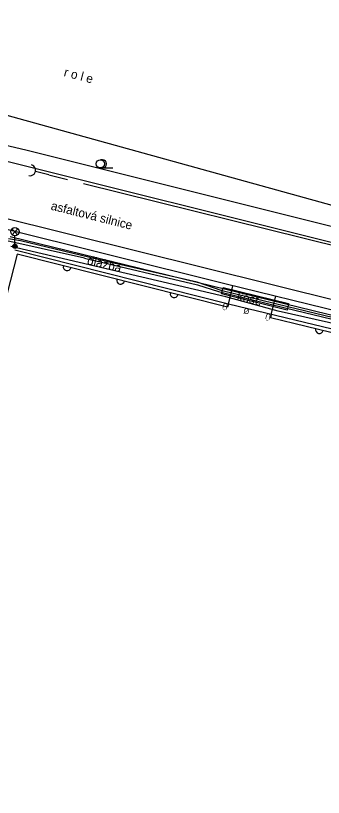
# Model space of a CAD drawing. Extents: x -614582 to -612559, y -1157748 to -1156203.
# Drawn here: x -612986.4 to -612958.6, y -1156940.7 to -1156869.8 of the extents above; entities that cross this region are included whole.
import ezdxf

# ---------------------------------------------------------------- set-up
doc = ezdxf.new("R2010")
doc.units = 0
for name, color, linetype in [('Vrstva 1', 7, 'Continuous'), ('Vrstva 11', 7, 'Continuous'), ('Vrstva 13', 7, 'Continuous'), ('Vrstva 17', 7, 'Continuous'), ('Vrstva 20', 7, 'Continuous'), ('Vrstva 22', 7, 'Continuous'), ('Vrstva 34', 7, 'Continuous'), ('Vrstva 36', 7, 'Continuous'), ('Vrstva 4', 7, 'Continuous'), ('Vrstva 47', 7, 'Continuous'), ('Vrstva 48', 7, 'Continuous'), ('Vrstva 5', 7, 'Continuous'), ('Vrstva 51', 7, 'Continuous'), ('Vrstva 7', 7, 'Continuous')]:
    doc.layers.add(name, color=color, linetype=linetype)

# ---------------------------------------------------------------- blocks, each defined once
blk = doc.blocks.new('SC3408')
at = {"layer": 'Vrstva 11'}
for points in [[(0, 5.5), (-2.5, 8)], [(0, 5.5), (2.5, 8)], [(0, 5.5), (-2.5, 3)], [(0, 5.5), (2.5, 3)], [(0, -5.5), (0, 2)]]:
    blk.add_lwpolyline(points, dxfattribs=at)
for centre, radius in [((0, 5.75), 3.75), ((0, -7.5), 2), ((0, -7.5), 1.6), ((0, -7.5), 1.2), ((0, -7.5), 0.8), ((0, -7.5), 0.4)]:
    blk.add_circle(centre, radius, dxfattribs=at)
blk = doc.blocks.new('PLOTZD')
at = {"layer": 'Vrstva 1'}
blk.add_arc((0, 0), 3.5, 0, 180, dxfattribs=at)
blk = doc.blocks.new('SC3420')
at = {"layer": 'Vrstva 48'}
for points in [[(0, 0), (-12.5, 0)], [(0, 0), (17.5, 0)]]:
    blk.add_lwpolyline(points, dxfattribs=at)
blk.add_arc((-17.5, 0), 5, 270, 90, dxfattribs=at)

msp = doc.modelspace()

# ---------------------------------------------------------------- linework, layer by layer
at = {"layer": 'Vrstva 17'}
msp.add_line((-612915.981, -1156905.926), (-613025.811, -1156878.626), dxfattribs=at)
at = {"layer": 'Vrstva 20'}
msp.add_line((-612917.45, -1156906.801), (-612986.931, -1156889.823), dxfattribs=at)
msp.add_line((-612917.45, -1156906.801), (-612986.931, -1156889.823), dxfattribs=at)
at = {"layer": 'Vrstva 22'}
for p, q in [((-613033.617, -1156870.174), (-612985.401, -1156881.987)), ((-612985.401, -1156881.987), (-612750.739, -1156940.65))]:
    msp.add_line(p, q, dxfattribs=at)
at = {"layer": 'Vrstva 34'}
for p, q in [((-612986.011, -1156890.196), (-612987.081, -1156890.016)), ((-612978.201, -1156892.056), (-612986.011, -1156890.196)), ((-612969.991, -1156893.936), (-612978.201, -1156892.056)), ((-612967.711, -1156894.716), (-612969.991, -1156893.936)), ((-612961.771, -1156896.176), (-612967.711, -1156894.716)), ((-612954.491, -1156897.926), (-612961.771, -1156896.176))]:
    msp.add_line(p, q, dxfattribs=at)
at = {"layer": 'Vrstva 36'}
msp.add_lwpolyline([(-612967.783, -1156895.007), (-612967.639, -1156894.425), (-612961.699, -1156895.885), (-612961.843, -1156896.467)], close=True, dxfattribs=at)
at = {"layer": 'Vrstva 4'}
for p, q in [((-612945.431, -1156890.396), (-613019.931, -1156869.776)), ((-613011.831, -1156876.856), (-612946.761, -1156893.076)), ((-612967.481, -1156894.096), (-612996.021, -1156886.996)), ((-612934.771, -1156902.106), (-612967.481, -1156894.096)), ((-612967.161, -1156895.926), (-612966.756, -1156894.274)), ((-612963.274, -1156896.871), (-612962.871, -1156895.225)), ((-612967.161, -1156895.926), (-612967.232, -1156896.218)), ((-612963.274, -1156896.871), (-612963.345, -1156897.163))]:
    msp.add_line(p, q, dxfattribs=at)
at = {"layer": 'Vrstva 47'}
for p, q in [((-612967.407, -1156895.263), (-612986.877, -1156890.714)), ((-612962.663, -1156896.564), (-612967.407, -1156895.263)), ((-612934.978, -1156902.854), (-612962.663, -1156896.564))]:
    msp.add_line(p, q, dxfattribs=at)
at = {"layer": 'Vrstva 48'}
msp.add_line((-612980.281, -1156885), (-612954.121, -1156891.496), dxfattribs=at)
at = {"layer": 'Vrstva 5'}
for p, q in [((-612967.161, -1156895.926), (-612986.511, -1156891.046)), ((-612986.295, -1156891.41), (-612987.804, -1156897.292)), ((-612967.233, -1156896.218), (-612986.295, -1156891.41)), ((-612934.551, -1156903.856), (-612967.161, -1156895.926)), ((-612934.622, -1156904.148), (-612963.345, -1156897.163))]:
    msp.add_line(p, q, dxfattribs=at)
at = {"layer": 'Vrstva 51'}
for p, q in [((-612980.213, -1156891.76), (-612988.091, -1156890.025)), ((-612980.213, -1156891.76), (-612988.091, -1156890.025)), ((-612980.213, -1156891.76), (-612969.957, -1156894.175)), ((-612980.213, -1156891.76), (-612969.957, -1156894.175)), ((-612969.957, -1156894.175), (-612968.046, -1156894.793)), ((-612969.957, -1156894.175), (-612968.046, -1156894.793)), ((-612968.046, -1156894.793), (-612962.005, -1156896.254)), ((-612968.046, -1156894.793), (-612962.005, -1156896.254)), ((-612962.005, -1156896.254), (-612951.044, -1156898.933)), ((-612962.005, -1156896.254), (-612951.044, -1156898.933))]:
    msp.add_line(p, q, dxfattribs=at)
at = {"layer": 'Vrstva 7'}
for points in [[(-612978.565, -1156882.846), (-612978.765, -1156882.846)], [(-612978.765, -1156883.579), (-612978.265, -1156883.579), (-612978.065, -1156883.579), (-612977.632, -1156883.579)]]:
    msp.add_lwpolyline(points, dxfattribs=at)
msp.add_circle((-612978.765, -1156883.212), 0.367, dxfattribs=at)
msp.add_arc((-612978.565, -1156883.212), 0.367, 270, 90, dxfattribs=at)

# ---------------------------------------------------------------- block references
at = {"layer": 'Vrstva 11', "xscale": 0.1, "yscale": 0.10000000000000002}
msp.add_blockref('SC3408', (-612986.511, -1156889.936), dxfattribs=at)
at = {"layer": 'Vrstva 48', "xscale": 0.09999999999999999, "yscale": 0.09999999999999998, "rotation": -13.946668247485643}
msp.add_blockref('SC3420', (-612983.436, -1156884.216), dxfattribs=at)
at = {"layer": 'Vrstva 5'}
for p, xscale, yscale, rotation in [((-612981.778, -1156892.549), 0.09999999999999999, 0.1, 165.84537699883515), ((-612976.929, -1156893.772), 0.09999999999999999, 0.1, 165.84537699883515), ((-612972.081, -1156894.995), 0.09999999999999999, 0.1, 165.84537699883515), ((-612958.914, -1156898.24), 0.1, 0.10000000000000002, 166.33227962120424)]:
    msp.add_blockref('PLOTZD', p, dxfattribs=dict(at, xscale=xscale, yscale=yscale, rotation=rotation))

# ---------------------------------------------------------------- texts
at = {"layer": 'Vrstva 13'}
for s, height, rotation, p in [('r o l e', 0.8, 345.28967, (-612982.13, -1156875.248)), ('asfaltová silnice', 0.79999, 345.97238, (-612983.306, -1156887.36)), ('dlažba', 0.8, 346.08762, (-612980.016, -1156892.305)), ('kost.', 0.8, 347.56814, (-612966.438, -1156895.578))]:
    msp.add_text(s, height=height, rotation=rotation, dxfattribs=at).set_placement(p)
at = {"layer": 'Vrstva 5'}
for s, p in [('Û', (-612967.161, -1156895.926)), ('Ø', (-612965.217, -1156896.399)), ('Û', (-612963.274, -1156896.872))]:
    msp.add_text(s, height=0.5, rotation=166.33228, dxfattribs=at).set_placement(p)

doc.saveas('drawing.dxf')
